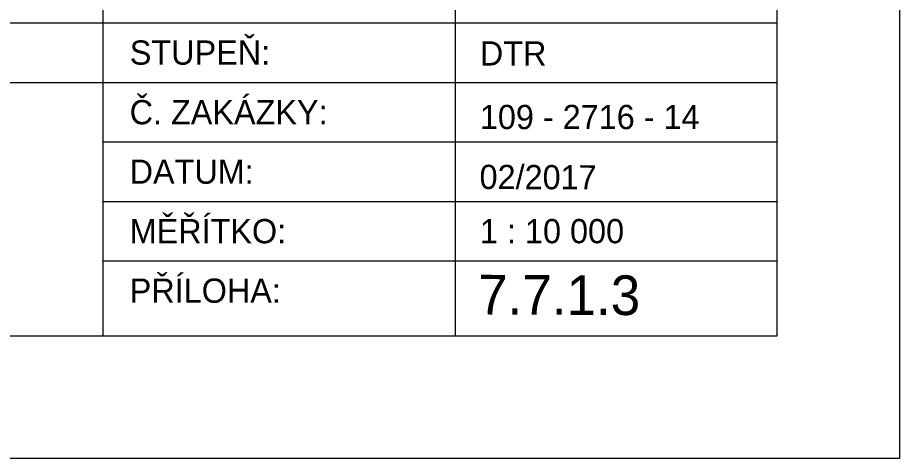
# Model space of a CAD drawing. Extents: x -498961 to -496861, y -1136989 to -1134019.
# Drawn here: x -497582 to -496861, y -1136989 to -1136629 of the extents above; entities that cross this region are included whole.
import ezdxf

# ---------------------------------------------------------------- set-up
doc = ezdxf.new("R2010")
doc.units = 0
doc.layers.add('04_ZPF_OP_ORGAN', color=7, linetype='Continuous')
doc.layers.add('16', color=7, linetype='Continuous')

msp = doc.modelspace()

# ---------------------------------------------------------------- linework, layer by layer
at = {"layer": '04_ZPF_OP_ORGAN'}
for p, q in [((-496861.36, -1134019.24), (-496861.36, -1136989.24)), ((-496861.36, -1136989.24), (-498961.36, -1136989.24))]:
    msp.add_line(p, q, dxfattribs=at)
at = {"layer": '16'}
for p, q in [((-497512.16, -1136889.26), (-497512.22, -1136334.77)), ((-497512.16, -1136889.26), (-497512.22, -1136334.77)), ((-496961.36, -1136889.24), (-496961.41, -1136334.73)), ((-496961.36, -1136889.24), (-496961.41, -1136334.73)), ((-497224.23, -1136889.28), (-497224.16, -1136487.83)), ((-497224.23, -1136889.28), (-497224.16, -1136487.83)), ((-498358.11, -1136633.56), (-496961.31, -1136633.54)), ((-498358.11, -1136633.56), (-496961.31, -1136633.54)), ((-498358.12, -1136682.12), (-496961.46, -1136682.29)), ((-498358.12, -1136682.12), (-496961.46, -1136682.29)), ((-497512.06, -1136730.84), (-496961.15, -1136730.84)), ((-497512.06, -1136730.84), (-496961.15, -1136730.84)), ((-497512.07, -1136779.42), (-496961.28, -1136779.51)), ((-497512.07, -1136779.42), (-496961.28, -1136779.51)), ((-497512.08, -1136828.01), (-496961.27, -1136827.99)), ((-497512.08, -1136828.01), (-496961.27, -1136827.99)), ((-498358.13, -1136889.16), (-496961.36, -1136889.24)), ((-498358.13, -1136889.16), (-496961.36, -1136889.24))]:
    msp.add_line(p, q, dxfattribs=at)

# ---------------------------------------------------------------- texts
for s, height, rotation, p in [('STUPEŇ:', 19.797, 359.99723, (-497490.42, -1136667.78)), ('DTR', 19.8, 359.99723, (-497204.27, -1136668.47)), ('Č. ZAKÁZKY:', 19.7933, 359.99723, (-497490.56, -1136716.45)), ('109 - 2716 - 14', 19.8, 359.99723, (-497204.28, -1136720.4)), ('DATUM:', 19.793, 359.99723, (-497490.57, -1136765.03)), ('02/2017', 19.8, 359.76285, (-497204.56, -1136769.29)), ('MĚŘÍTKO:', 19.793, 359.99723, (-497490.56, -1136813.62)), ('1 : 10 000', 19.8, 359.99723, (-497204.16, -1136813.6)), ('PŘÍLOHA:', 19.793, 359.99723, (-497490.5, -1136862.21)), ('7.7.1.3', 32.4, 359.76154, (-497205.73, -1136871.74))]:
    msp.add_text(s, height=height, rotation=rotation, dxfattribs=at).set_placement(p)

doc.saveas('drawing.dxf')
